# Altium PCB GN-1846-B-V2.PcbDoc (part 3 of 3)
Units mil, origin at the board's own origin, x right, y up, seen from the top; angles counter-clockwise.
Board outline 11621.85 x 2979.29 mil, 2 copper layers (Top, Bottom), stack 12.7 mil thick; 356 components, 252 nets, 1224 pads, 826 vias.
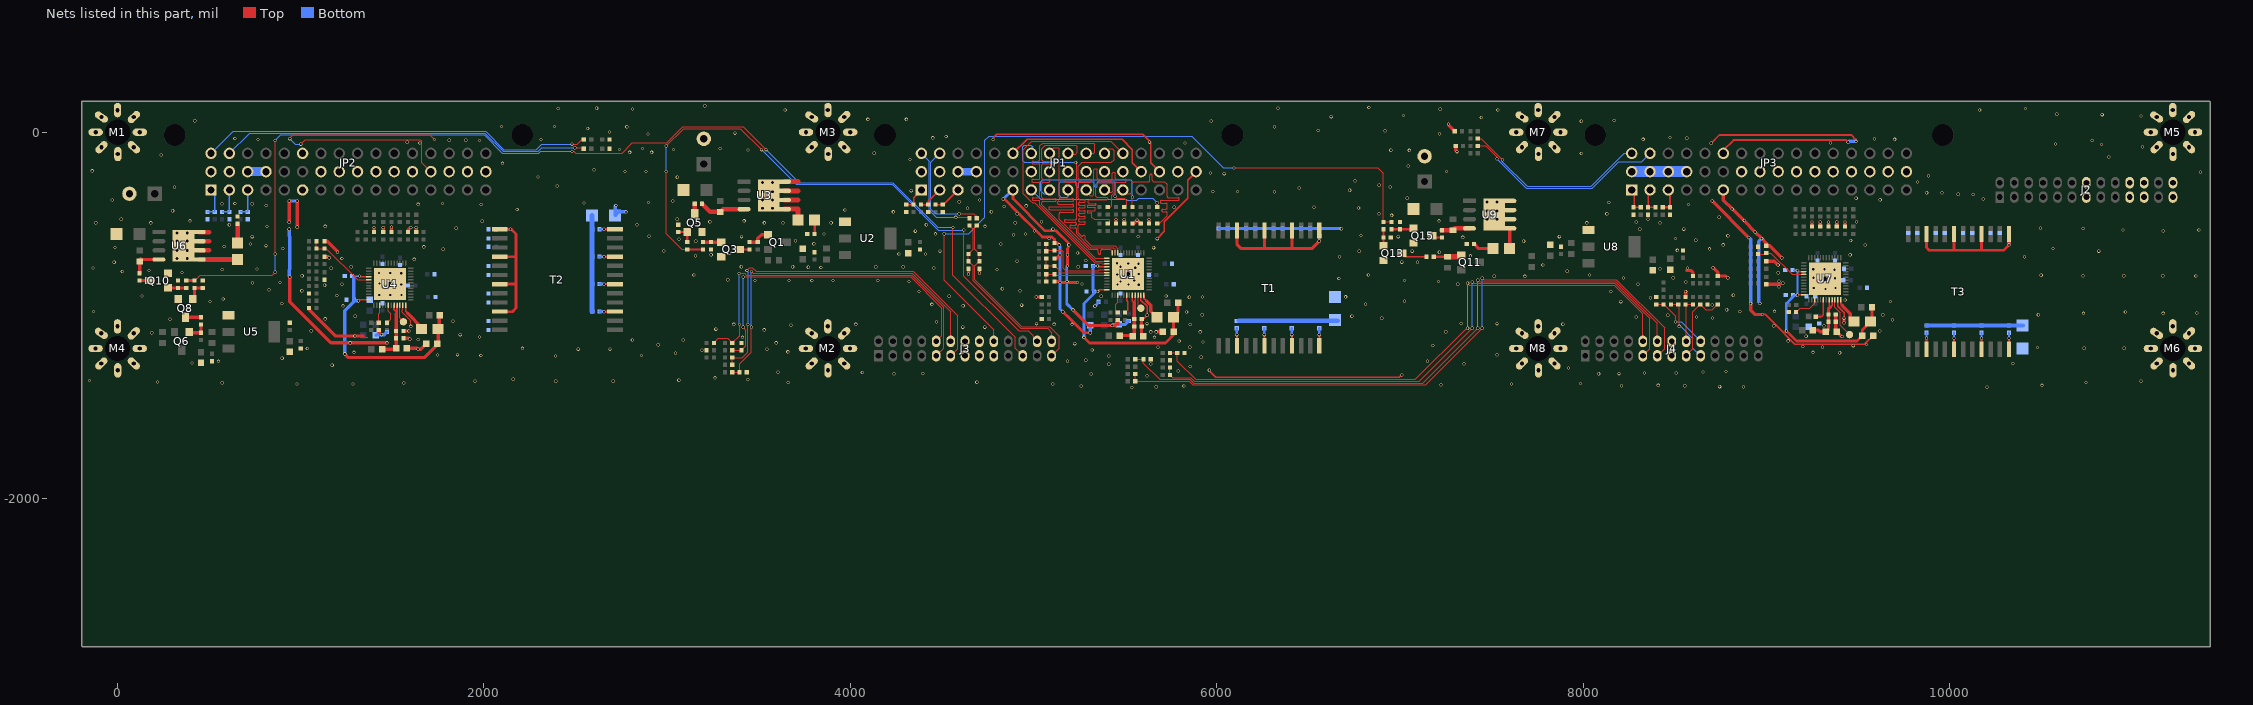
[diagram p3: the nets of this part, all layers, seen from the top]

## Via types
v1: diameter 18, hole 12, Top to Bottom, 786 vias
v2: diameter 24, hole 16, Top to Bottom, 28 vias
v3: diameter 30, hole 20, Top to Bottom, 6 vias
v4: diameter 40, hole 30, Top to Bottom, 6 vias

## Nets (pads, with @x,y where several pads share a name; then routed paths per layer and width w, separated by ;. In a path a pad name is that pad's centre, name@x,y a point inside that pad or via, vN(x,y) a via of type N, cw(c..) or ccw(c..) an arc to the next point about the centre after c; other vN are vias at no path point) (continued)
GND: C1.2 C2.2 C3.2 C4.2 C5.2 C6.2 C7.2 C8.2 C9.2 C10.2 C11.2 C12.2 C13.2 C14.2 C15.2 C16.2 C17.2 C18.1 C19.1 C20.2 C21.1 C22.1 C23.1 C24.1 C25.1 C26.1 C27.1 C28.2 C29.2 C30.2 C31.2 C32.1 C33.1 C34.2 C35.2 C36.2 C37.2 C38.2 C39.2 C40.2 C41.2 C42.2 C43.2 C44.2 C45.2 C46.2 C47.2 C48.2 C49.2 C50.2 C51.1 C52.1 C53.1 C54.1 C55.1 C56.1 C57.1 C58.1 C59.2 C60.2 C61.1 C62.2 C63.2 C64.2 C65.2 C66.1 C67.1 C68.2 C69.2 C70.2 C71.2 C72.2 C73.2 C74.2 C75.2 C76.2 C77.2 C78.2 C79.2 C80.2 C81.2 C82.2 C83.2 C84.2 C85.2 C86.1 C87.1 C88.1 C89.1 C90.1 C91.1 C92.1 C93.1 C94.2 C95.1 C96.2 C97.2 C98.2 C99.2 C100.1 C101.1 C102.2 C300.2 C301.2 C302.2 J2.13 J2.14 J2.19 J2.20 J2.21 J2.22 J2.25 J2.26 J3.13 J3.14 J3.15 J3.16 J3.17 J4.13 J4.14 JP1.A6 JP1.B7 JP1.B8 JP1.B9 JP1.B10 JP1.B11 JP1.B12 JP1.B13 JP1.B14 JP1.B15 JP1.B16 JP1.C6 JP2.A6 JP2.B7 JP2.B8 JP2.B9 JP2.B10 JP2.B11 JP2.B12 JP2.B13 JP2.B14 JP2.B15 JP2.B16 JP2.C6 JP3.A6 JP3.B7 JP3.B8 JP3.B9 JP3.B10 JP3.B11 JP3.B12 JP3.B13 JP3.B14 JP3.B15 JP3.B16 JP3.C6 M1.2 M1.3 M1.4 M1.5 M1.6 M1.7 M1.8 M1.9 M2.2 M2.3 M2.4 M2.5 M2.6 M2.7 M2.8 M2.9 M3.2 M3.3 M3.4 M3.5 M3.6 M3.7 M3.8 M3.9 M4.2 M4.3 M4.4 M4.5 M4.6 M4.7 M4.8 M4.9 M5.2 M5.3 M5.4 M5.5 M5.6 M5.7 M5.8 M5.9 M6.2 M6.3 M6.4 M6.5 M6.6 M6.7 M6.8 M6.9 M7.2 M7.3 M7.4 M7.5 M7.6 M7.7 M7.8 M7.9 M8.2 M8.3 M8.4 M8.5 M8.6 M8.7 M8.8 M8.9 Q3.2 Q5.2 Q8.2 Q10.2 Q13.2 Q15.2 R17.1 R20.1 R22.1 R28.2 R32.2 R33.2 R38.2 R41.2 R44.2 R47.2 R49.2 R51.1 R58.1 R60.1 R77.1 R78.1 R82.1 R88.2 R92.2 R93.2 R98.2 R101.2 R103.2 R107.2 R109.2 R111.1 R118.1 R120.1 R137.1 R138.1 R142.1 R148.2 R152.2 R153.2 R158.2 R161.2 R164.2 R167.2 R169.2 R171.1 R178.1 R180.1 R202.2 R203.2 R204.2 R205.2 R208.2 R209.2 R300.2 R301.2 R302.2 R303.2 R304.2 R305.2 R306.2 R307.2 R308.2 U1.47 U1.49 U2.1 U4.47 U4.49 U5.1 U7.47 U7.49 U8.1 | length 16168.3
  Top w5: v1@940,-32.5 957.5,-15 1705,-15 v1(1730,-40) ; v1(1000,-65) 1023.5,-41.5 1651.5,-41.5 1660,-50 1660,-59.11 1660,-165.51 JP2.B13@1709.84,-215.35 ; 1343.5,-1112 1350,-1118.5 1365.17,-1118.5
  Top w6: U4.47@1556.67,-944.17 1555.41,-945.43 1555.41,-969.59 1555,-970 1555,-984.04 1600,-1029.04 v1(1600,-1060)
  Top w8: v1(4780,-40) 4780,-30 4800,-10 5595,-10 5636.05,-51.05 5640,-55 5640,-167.56 JP1.B14@5687.8,-215.35 ; JP1.A6@4887.8,-115.35 4964.65,-38.5 5483.5,-38.5 5540,-95 5540,-167.56 JP1.B13@5587.8,-215.35 ; U1.47@5586.67,-889.17 5586.67,-917.12 5620.76,-951.22 v1(5620.76,-999.24) C1.2@5590,-1030 ; v1(5675,-581) 5714,-542 5714,-488.26 5841.57,-360.69 5841.57,-261.57 JP1.B16@5887.8,-215.35 ; v1(5960,-1299.11) 5960,-1303.5 5995,-1338.5 6997.29,-1338.5 v1(7010.79,-1325) ; v1(8980,-995) 8994.54,-995 9048.67,-1049.12 9156.04,-1156.5 9475,-1156.5 9538.03,-1156.5 9541.21,-1153.32 C81.2@9583.53,-1111 ; U7.47@9390.91,-915.59 9390.91,-950.91 9425,-985 v1(9425,-1015)
  Top w10: v1(8700,-60) 8745,-15 9465,-15 9490,-40 v1(9490,-50) ; JP3.A6@8765.75,-99.25 8822,-43 9350.79,-43 9435.75,-43 v1(9447.75,-55)
  Top w15: v1(4835,-365) 4841.67,-365 4916.23,-439.56 5010.39,-533.72 5048.17,-571.5 5085.79,-571.5 5101.5,-571.5 5115,-585 C27.1@5115,-605 5130,-605 v1(5140,-615) ; JP1.C6@4887.8,-315.35 4887.8,-362.8 5063.5,-538.5 5105.79,-538.5 5123.91,-538.5 5190,-604.59 5190,-614.11 5190,-629.59 5185,-634.59 5185,-669 v1(5185,-730) ; v1(5015,-900) R41.2@5045,-900 ; v1(5160,-980) 5168.5,-988.5 5168.5,-988.91 5181.09,-1001.5 5181.5,-1001.5 5219.55,-1039.55 5275,-1095 v1(5310,-1095)
  Top w18: v1(937,-491) 937,-380 939.5,-377.5 v1@942,-375 ; v1(940,-790) 940,-925.46 1164.54,-1150 v1(1270,-1150) v1(1470,-1150) ; v1@980,-520 v1(980,-519) v1(980,-375) ; R88.2@1045,-960 1045,-970 1187,-1112 v1(1295,-1112) 1340,-1112 ; C66.1@1130,-680 1150,-680 v1(1155,-685) ; C61.1@1130,-595 1145,-595 1200,-650 v1(1200,-655) ; R109.2@1400,-545 v1(1400,-520) ; R77.1@1425,-1080 1425,-1090 v1(1440,-1105) ; R107.2@1450,-545 v1(1450,-520) ; R103.2@1495,-545 v1(1495,-519.11) ; C35.2@1560,-1125 1590,-1125 v1(1595,-1130) ; C36.2@1560,-1085 v1(1590,-1085) ; C37.2@1579.53,-1180 1635,-1180 v1(1640,-1185) 1655.47,-1185 C47.2@1685.47,-1155 ; R98.2@1585,-545 1585,-535 v1(1600,-520) ; R93.2@1630,-545 v1(1630,-520) ; v1(4645,-775) R205.2@4645,-745 ; v1(4705,-770) R204.2@4705,-745 ; C33.1@5115,-815 5140,-815 v1(5145,-820) 5183.5,-820 v1(5240,-820) ; C32.1@5115,-690 5125,-690 v1(5145,-670) ; v1(5215,-970) 5300,-1055 v1(5430,-1055) 5450,-1055 5460,-1045 R20.1@5460,-1025 ; R49.2@5450,-499 5450,-477.79 v1(5450.79,-477) ; R47.2@5495,-499 5495,-477.79 v1(5495.79,-477) ; R44.2@5540,-499 5546,-499 v1(5565,-480) 5566,-480 R38.2@5585,-499 ; C3.2@5590,-1110 C1.2@5590,-1030 ; R33.2@5630,-499 5630,-477.79 v1(5630.79,-477) ; v1(5670,-1090) C13.2@5705.47,-1090 ; v1(7265,45) 7265,40 R208.2@7300,5 ; R209.2@7305,-75 7305,-99 v1(7312,-106) ; R138.1@8560,-900 v1(8560,-870) ; 8565,-755 8570.79,-755 8590,-755 8600,-765 R148.2@8600,-785 ; v1(8705,-375) v1(8905,-575) ; v1(8710,-740) 8735,-765 R161.2@8735,-785 8780,-785 v1(8790,-795) ; JP3.C6@8765.75,-315.35 8765.75,-370.75 8814.05,-419.05 8878.89,-483.89 v1(8940,-545) v1(8975,-580) 9000,-605 C95.1@9000,-620 9020,-620 v1(9085,-685) ; JP3.A6@8765.75,-115.35 JP3.A6@8765.75,-99.25 ; v1(8915,-935) 8915,-972.11 8937.89,-995 v1(8980,-995) ; C101.1@9000,-830 9070,-830 9075,-830 ; C100.1@9000,-705 9045,-705 v1(9065,-725) ; R169.2@9250,-515 v1(9250,-490) ; R167.2@9295,-515 v1(9295,-490) ; R164.2@9340,-515 v1(9340,-490) ; C69.2@9380,-995 9380,-1085.47 C71.2@9384.53,-1090 9409.53,-1115 v1(9415,-1115) ; R158.2@9385,-515 v1(9385,-490) ; v1(9425,-1040) v1(9425,-1015) ; R153.2@9430,-515 v1(9430,-490)
  Bottom w5: v1(940,-35) 970,-65 v1(1000,-65)
  Bottom w15: v1(4835,-365) 4884.65,-315.35 JP1.C6@4887.8,-315.35 ; 5145,-625 v1(5145,-670) v1(5145,-820) 5145,-965 v1(5160,-980) ; v1(5185,-730) 5181.5,-733.5 5181.5,-815 5181.5,-936.5 v1(5215,-970) ; v1(5335,-950) 5355,-930 C6.2@5355,-925 ; C21.1@6010,-525 v1@6678.79,-525
  Bottom w18: v1(937,-530) 937,-567 940,-570 940,-749.47 937,-752.47 937,-787 v1(940,-790) ; v1@942,-375 v1(980,-375) ; C50.2@1410,-1109.53 1414.53,-1105 v1(1440,-1105) 1455.47,-1105 C49.2@1470,-1090.47 ; v1(2720,-400) 2716,-404 C60.2@2716,-455 2730,-441 2730,-440 2735,-435 v1(2775,-435) ; v1(5310,-1095) C7.2@5310,-1054.53 ; v1(5430,-1055) 5435.47,-1049.53 C16.2@5465,-1049.53 5500.94,-1049.53 C15.2@5520,-1030.47 ; v1(8905,-575) 8915,-585 v1(8915,-935) ; v1(8965,-935) 8965,-932.47 8958.76,-926.24 8958.76,-596.24 v1(8975,-580) ; v1(9447.75,-55) 9452.75,-50 v1(9490,-50)
  other v1: 5536,-1394.11 10205.79,-1392 8875.79,-1390 5670,-1389.11 8745.79,-1389 5260.79,-1386 5820.79,-1385 8210,-1384.11 8555,-1384.11 8410.79,-1382 10505.79,-1382 7225,-1379.11 979,-1374.11 1285,-1374.11 5105,-1374.11 7610,-1374.11 7985.79,-1372 1562,-1369.11 570.79,-1368 3660.79,-1366 10745.79,-1366 4690.79,-1365 218,-1364.11 2705.79,-1360 11045.79,-1360 1951,-1359.11 2392,-1359.11 -154.21,-1356 3064,-1354.11 3440,-1350 2160,-1349.11 3260.79,-1341 5620,-1329.11 5315,-1320 4238,-1319.11 8085,-1319.11 8195.79,-1318 4395.79,-1317 8335,-1314.11 8509,-1314.11 4065.79,-1312 3605,-1310 8655,-1309.11 8780.79,-1306 5790,-1304.11 7921,-1287 5856,-1279.11 1170.79,-1272 5410.79,-1267 5640,-1265 7350,-1264.11 10345.79,-1263 405.79,-1260 550.79,-1251 5185.79,-1250 7150.79,-1250 5285,-1245 898,-1234.11 5915.79,-1228 2390.79,-1222 5411,-1222.11 1983,-1219.11 2860,-1219.11 1745.79,-1216 7530.79,-1215 1855,-1214.11 3045.79,-1207 9400.79,-1204 1290.79,-1202 9255.79,-1202 3659,-1199.11 3190,-1190 5320,-1189.11 3545,-1185 2515,-1184.11 2688,-1184.11 1035.79,-1181 2210,-1180 10736,-1179.11 10955,-1179.11 10480.79,-1175 5680,-1174.11 5853,-1174.11 9307,-1174.11 9200,-1170 9475,-1165 7179,-1164.11 2950.79,-1160 9547,-1159.11 5225,-1154.11 3595,-1150 5925.79,-1145 5795,-1140 9120,-1139.11 2810,-1134.11 3088,-1134.11 1640.79,-1132 3410.79,-1120 5660,-1120 1975.79,-1118 9218,-1114.11 1870.79,-1105 185.79,-1095 5640,-1090 5910,-1090 7250,-1089.11 9620,-1085 1057,-1084.11 3530,-1079.11 3265.79,-1075 4614,-1064.11 4734,-1064.11 9040.79,-1057 9315,-1057.11 3675.79,-1054 5855.79,-1050 3363,-1049.11 4030,-1049.11 5113,-1049.11 5210,-1049.11 7890,-1048 5015.79,-1045 5620,-1045 7530.79,-1045 7335,-1044.11 4470,-1035 1830.79,-1032 9690,-1024.11 285.79,-1021 1133,-1019.11 6901,-1016 8707,-1014.11 8290,-1009.11 8619,-1009.11 1297,-1005 6738,-1005 8462,-999.11 9635.79,-997 5920.79,-996 10485.79,-996 10732,-989.11 11168,-989.11 11350.79,-987 5835.79,-982 10960.79,-982 -132,-979.11 8856,-979.11 9045.79,-978 8784,-969.11 1230.79,-948 4615.79,-947 4935,-944.11 8705.79,-943 4445,-940 6812,-939 895.79,-935 8205.79,-925 504,-924.11 9678,-924.11 7025.79,-923 9430.79,-916 575.79,-910 8368,-904.11 5850.79,-901 5923,-899.11 6704,-899 4540,-895 5370,-895 133,-894.11 5724,-894.11 1195.79,-891 8820.79,-890 1428,-889 1488,-889 1549,-889 4375,-870 8150.79,-870 1005.79,-865 4925.79,-865 825.79,-860 9324,-856 4830,-854.11 9379,-851 9259,-850 9070,-844.11 1130,-835 5575,-833 1548,-832 5458,-832 5519,-832 1225,-830 7315.79,-830 8300,-830 5265,-829.11 1429,-826 9090.79,-825 735.79,-822 885.79,-820 8560.79,-818 4320,-815 5183.5,-815 5475,-815 7210.79,-815 9070,-814.11 5550,-810 7025.79,-810 3480,-809.11 3665,-809.11 3790,-809.11 3905,-809.11 4150,-809.11 3330.79,-805 6667,-799.11 9376,-797 8220.79,-796 9258,-795 8493,-794.11 7682,-787.11 7515,-786.11 11345.79,-785 1007,-784.11 10729,-784.11 10952,-784.11 11165,-784.11 10500.79,-781 3145.79,-779 6828,-779.11 8035,-779.11 5457,-776 5575,-774 1548,-770 1488,-769 1427,-768 9065.79,-767 350.79,-766 25.79,-760 7914,-759.11 170.79,-755 9372,-751 570.79,-750 4800.79,-750 9257,-748 9318,-748 760.79,-747 8420,-745 1165.79,-743 -134.21,-741 4455.79,-741 8570.79,-741 5555,-740 3839,-739.11 3770.79,-737 3685,-735 5475,-735 1275,-734.11 3405,-734.11 4139,-734.11 4289,-734.11 5244,-734.11 7780.79,-725 5573,-718 5517,-717 5456,-715 -19.21,-710 7095.79,-710 7010,-709.11 4910,-704.11 5285,-700 1619,-694.11 1224,-689.11 6671,-680 10410,-680 7385.79,-675 3155,-674.11 3240,-669.11 5185.79,-669 9458,-669.11 4265,-665 4410,-665 3340,-660 5240.79,-659 7215.79,-655 6778,-650 4489,-649.11 7068,-649.11 10815,-649.11 2980.79,-648 8515,-645 1777,-639.11 8690.79,-637 900.79,-635 10565.79,-635 5655.79,-630 -15,-629.11 1670.79,-626 582,-624.11 810,-619.11 9540.79,-616 8765.79,-615 5193,-614.11 725,-610 4820.79,-610 3800.79,-609 3155.79,-595 7675.79,-595 3700.79,-593 9460.79,-591 8615,-590 3065,-584.11 5085.79,-580 8505,-580 7343,-574.11 735,-570 3405.79,-570 6990.79,-570 7870.79,-570 5572,-569.11 2900.79,-568 8790.79,-565 6788,-564.11 4890.79,-560 3855.79,-556 4955.79,-556 4465,-555 4355,-540 5005,-539.11 11168,-539.11 10948,-534.11 11362,-534.11 5105.79,-530 8310,-530 8550,-529.11 6680.79,-527 10730.79,-526 1849,-524.11 10497,-524.11 815,-515 1133,-514.11 4735,-514.11 610,-505 2835.79,-505 3155.79,-505 4415,-505 180.79,-495 3530.79,-495 8020,-495 -120,-494.11 3632,-494.11 3895,-494.11 4900,-494.11 8420,-494.11 8290.79,-490 3233,-489.11 5044,-489.11 9493,-489.11 1990.79,-486 395,-484.11 3420,-484.11 7214,-484.11 8880.79,-482 20,-475 3055,-475 8355,-475 8744,-464.11 6955,-454.11 4910.79,-445 6885.79,-445 8130,-445 4235,-435 4770,-434.11 300,-429.11 3970,-425 2180.79,-422 8814,-419.11 4640,-415 6775,-414.11 6530.79,-410 5768,-409.11 4840,-405 4960.79,-402 810.79,-400 8575.79,-395 1640.79,-394 1985,-394.11 570,-390 735,-390 640,-389.11 1773,-389.11 2545.79,-386 2898,-384.11 8140,-384.11 4595,-380 937,-375 3030,-375 -29.21,-370 4705,-370 9622,-369.11 10185,-365 9490.79,-361 7040.79,-360 10130.79,-340 10048,-339.11 9875.79,-330 9960,-330 6315.79,-325 5979,-324.11 6114,-324.11 4333,-319 6725.79,-317 6450.79,-305 310.79,-300 6948,-299.11 2400,-294.11 6887,-289.11 9825.79,-272 6755,-265 3055.79,-246 2295,-245 9885.79,-238 6040.79,-226 5965.79,-223 11370.79,-219 2770,-214.11 2884,-214.11 7255,-214.11 -139.21,-211 2600.79,-205 7046,-184.11 2100.79,-170 4326,-149 10870,-135 238,-124.11 7990.79,-116 4130.79,-115 2795,-110 2915,-110 7052,-99.11 6950.79,-98 3440.79,-97 2740,-94.11 3034,-94.11 2865,-89.11 3290,-89.11 11054,-79.11 10830.79,-67 10579,-64.11 1650,-59.11 5827,-59.11 9350.79,-57 1580.79,-55 5633,-54.11 1975.79,-45 10780,-45 1810,-44.11 1900,-44.11 765.79,-40 2310.79,-40 8328,-39.11 9701,-39.11 9590.79,-36 640,-34.11 8565.79,-33 4450,-31 8475,-29.11 4523,-23 2895,-10 7216,-8 3370.79,-5 2685,0.89 6919,8 6554,9 2565.79,20 2780,30 6315.79,30 2095,30.89 2385,30.89 7990.79,60 5970,60.89 420.79,63 8170.79,64 4095.79,70 4305.79,70 7445,80 6625,85 11045.79,88 7020,90.89 10834,95.89 10585.79,98 3644,120.89 7535,120.89 10165,120.89 7220.79,125 2810.79,127 2405.79,129 10415,130 2615,130.89 6335,130.89 6830.79,135 3205,145
MAC_MDC: C32.2 R30.1 R37.2 U1.30 | length 393
  Top w5: R30.1@5070,-690 R37.2@5070,-735 5075,-730 C32.2@5115,-730 5151.34,-766.34 U1.30@5400.84,-766.34
MAC_MDIO: C33.2 R31.1 R39.2 U1.31 | length 377.9
  Top w5: R31.1@5070,-815 R39.2@5070,-775 C33.2@5105,-775 ; C33.2@5107.92,-772.08 C33.2@5105,-775 ; U1.31@5400.84,-782.08 5122.08,-782.08 C33.2@5115,-775 C33.2@5105,-775
NetB1_1: B1.1 C1.1 C2.1 C3.1 U1.44 U1.45 | length 344.6
  Top w8: U1.44@5539.42,-889.17 5539.42,-919.42 5550.47,-930.47 5550.47,-924.53 5555.17,-919.83 U1.45@5555.17,-889.17
  Top w18: B1.1@5479.53,-1115 5479.53,-1110 5540.47,-1110 5550.47,-1110 5550.47,-930.47
NetB2_2: B2.2 C11.1 C12.1 C13.1 L1.1 U1.28 U1.36 | length 1282.6
  Top w8: v1(5350,-870) 5359.18,-860.82 U1.36@5400.84,-860.82 ; v1(5350,-730) 5355,-735 5355.16,-734.84 U1.28@5400.84,-734.84
  Top w16: v1(5275,-1120) 5305,-1150 5720,-1150 5772.26,-1097.74 C13.1@5764.53,-1090 5764.53,-1010.47 L1.1@5765,-1010 5789.53,-985.47 B2.2@5789.53,-930
  Bottom w12: C12.1@5325,-730 v1(5350,-730) ; C11.1@5330,-870 v1(5350,-870)
  Bottom w16: v1(5275,-1120) 5275,-1090 ; 5275,-1100 5275,-1090 ; C11.1@5325,-864.53 C12.1@5325,-730 ; C11.1@5330,-870 5330,-880 5275,-935 5275,-1090
NetB4_1: B4.1 C35.1 C36.1 C37.1 U4.44 U4.45 | length 356.4
  Top w10: U4.44@1509.42,-944.17 1509.42,-969.42 1525,-985 ; 1525.17,-984.83 U4.45@1525.17,-944.17
  Top w18: B4.1@1444.53,-1185 1515.47,-1185 C37.1@1520.47,-1180 1520.47,-989.53
NetB5_2: B5.2 C45.1 C46.1 C47.1 L2.1 U4.28 U4.36 | length 1349
  Top w8: v1(1315,-920) 1320,-920 1324.18,-915.82 U4.36@1370.84,-915.82 ; v1(1320,-785) 1325,-790 1330,-790 1330.16,-789.84 U4.28@1370.84,-789.84
  Top w18: v1(1240,-1210) 1260,-1230 1675,-1230 1747.26,-1157.74 1750,-1155 L2.1@1750,-1075
  Top w20: B5.2@1754.53,-1005 1759.53,-1005 1765,-1005 1764.76,-1005.24 1755,-1015 1755,-1075 L2.1@1755,-1080
  Top w24: L2.1@1745,-1075 1745,-1070 L2.1@1750,-1075 L2.1@1755,-1080
  Bottom w8: C45.1@1289.53,-790 1294.53,-785 v1(1320,-785)
  Bottom w18: v1(1240,-1210) 1240,-974.53 1290,-924.53 C46.1@1290,-915 1295,-920 v1(1315,-920) ; C46.1@1289.53,-915 C45.1@1289.53,-790
NetB7_1: B7.1 C69.1 C70.1 C71.1 U7.44 U7.45 | length 312.7
  Top w8: U7.44@9343.66,-915.59 9343.66,-948.66 9350,-955 9359.41,-945.59 U7.45@9359.41,-915.59
  Top w18: B7.1@9254.53,-1080 9285,-1080 9295,-1090 9320.47,-1090 9322.97,-1092.5 9325.47,-1095 9327.97,-1092.5 9340,-1080.47 9340,-965 9350,-955
NetB8_2: B8.2 C79.1 C80.1 C81.1 L3.1 U7.28 U7.36 | length 1080.7
  Top w8: v1(9170,-890) 9173.39,-886.61 U7.36@9205.04,-886.61 ; v1(9170,-755) 9175,-755 9180.63,-760.63 U7.28@9205.04,-760.63
  Top w15: v1(9110,-1085) 9165,-1140 9495.47,-1140 C81.1@9524.47,-1111 9524.47,-1079.53 L3.1@9570,-1034 9577.53,-1026.47 B8.2@9577.53,-956
  Bottom w12: C79.1@9153,-755 v1(9170,-755) v1(9170,-890)
  Bottom w15: v1(9110,-1085) 9110,-935 9155,-890 v1(9170,-890)
NetC17_1: C17.1 T1.1 T1.4 T1.7 T1.10 | length 927.6
  Top w12: v1(6560,-595) 6560.79,-594.21 T1.1@6560.79,-535.84
  Top w18: T1.10@6110.79,-535.84 6110.79,-610.79 6135,-635 6260,-635 ; T1.7@6260.79,-535.84 6260.79,-634.21 6260,-635 ; 6410.79,-624.21 T1.4@6410.79,-535.84 6410.79,-634.21 6410,-635 ; v1(6560,-595) 6520,-635 6410,-635 ; 6260,-635 6410,-635
  Bottom w12: v1(6560,-595) C17.1@6560,-565
NetC20_1: C20.1 R1.2 R2.2 R3.2 R11.2 | length 540
  Bottom w24: R1.2@6120,-1030 6645,-1030 C20.1@6660,-1030
NetC27_2: C27.2 R10.2 R12.2 U1.29 | length 487.1
  Top w5: R12.2@5070,-600 5070,-645 C27.2@5115,-645 ; C27.2@5125,-645 C27.2@5115,-645 ; U1.29@5400.84,-750.59 5360,-750.59 5354.25,-756.34 5176.34,-756.34 5161.5,-741.5 5161.5,-651.5 5155,-645 C27.2@5115,-645
NetC59_1: C59.1 T2.1 T2.4 T2.7 T2.10 | length 861.6
  Top w15: T2.10@2085.84,-979.21 2086.63,-980 2155,-980 2175,-960 2175,-830 ; T2.7@2085.84,-829.21 2174.21,-829.21 2175,-830 ; T2.4@2085.84,-679.21 2174.21,-679.21 2175,-680 ; T2.1@2085.84,-529.21 2144.21,-529.21 v1(2145,-530) 2150,-530 2175,-555 2175,-680 ; 2175,-830 2175,-680
  Bottom w15: C59.1@2065,-530 v1(2145,-530)
NetC60_1: C60.1 R61.2 R62.2 R63.2 R69.2 | length 524.5
  Bottom w28: C60.1@2590,-455 2590,-978.41 R61.2@2590.8,-979.21
NetC61_2: C61.2 R71.2 R72.2 U4.29 | length 396.5
  Top w5: R72.2@1085,-595 R71.2@1085,-635 C61.2@1130,-635 1140,-635 1310.59,-805.59 U4.29@1370.84,-805.59
NetC85_1: C85.1 T3.1 T3.4 T3.7 T3.10 | length 810.6
  Top w15: T3.10@9875,-555.04 9875,-630 9890,-645 10025,-645 ; T3.7@10025,-555.04 10025,-645 ; T3.4@10175,-555.04 10175,-640 10170,-645 ; T3.1@10325,-555.04 v1(10325,-615) 10295,-645 10170,-645 ; 10025,-645 10170,-645
  Bottom w15: v1(10325,-615) C85.1@10325,-590
NetC94_1: C94.1 R121.2 R122.2 R123.2 R129.2 | length 525
  Bottom w24: R121.2@9875,-1055 C94.1@10400,-1055
NetC95_2: C95.2 R131.2 R132.2 U7.29 | length 340.3
  Top w5: R132.2@8955,-625 R131.2@8955,-665 8995,-665 C95.2@9000,-660 9025,-660 9141.38,-776.38 U7.29@9205.04,-776.38
NetJ3_9: J3.9 R74.2 R75.2 | length 1989.8
  Top w5: R74.2@3255,-1150 3280,-1125 3330,-1125 R75.2@3355,-1150 3395,-1110 v1(3395,-1050) ; v1(3393.61,-771.39) 3394.5,-770.5 3422.92,-770.5 3432.42,-780 4334.14,-780 4510,-955.86 4510,-1178.98 J3.9@4468.5,-1220.47
  Bottom w5: v1@3393.61,-1048.61 v1(3393.61,-771.39)
NetJ3_10: J3.10 R76.2 R78.2 | length 1811.8
  Top w5: R76.2@3355,-1190 R78.2@3400,-1190 ; R78.2@3405,-1190 3430,-1165 3430,-1080 v1(3415,-1065) ; v1(3415,-790) 4330,-790 4500,-960 4500,-1110.24 J3.10@4468.5,-1141.73
  Bottom w5: v1(3415,-1065) v1(3415,-790)
NetJ3_11: J3.11 R79.2 R80.2 | length 2081
  Top w5: R80.2@3355,-1270 R79.2@3355,-1230 3410,-1230 3440,-1200 v1(3440,-1050) ; v1(3435,-755) 3450,-740 3465,-740 3485,-760 4342.43,-760 4585,-1002.57 4585,-1182.72 J3.11@4547.24,-1220.47
  Bottom w5: v1(3435,-755) 3443.5,-763.5 v1@3443.5,-1046.5
NetJ3_12: J3.12 R81.2 R82.2 | length 1957.6
  Top w5: R81.2@3355,-1310 R82.2@3395,-1310 3395,-1265 3460,-1200 v1(3460,-1065) ; v1(3460,-760) 3470,-770 4338.28,-770 4547.24,-978.96 J3.12@4547.24,-1141.73
  Bottom w5: v1(3460,-1065) v1(3460,-760)
NetJ3_18: J3.18 R170.2 R179.2 | length 3957.2
  Top w5: v1(4513,-554) 4513,-808 4783.47,-1078.47 J3.18@4783.47,-1141.73 ; v1(6095,-195) 6880,-195 6910,-225 R170.2@6910,-490 R179.2@6955,-490
  Bottom w5: v1(4513,-554) 4646,-554 4735,-465 4735,-45 4758,-22 5862.86,-22 6035.86,-195 v1(6095,-195)
NetJ3_21: J3.21 R110.2 R119.2 | length 6131.9
  Top w5: R110.2@420,-810 450,-780 845,-780 v1(860,-765) ; v1(860,-665) v1(860,-45) ; v1(2480,-105) 2490,-105 2500,-115 2753.5,-115 2810,-58.5 2997.36,-58.5 3085.86,30 3415,30 v1(3540,-95) ; v1(4560,-520) 4560,-780 4900,-1120 4900,-1179.53 J3.21@4940.95,-1220.47
  Top w18: R119.2@375,-810 R110.2@420,-810
  Bottom w5: v1(860,-765) v1(860,-665) ; v1(860,-45) 890,-15 2000.86,-15 2100.86,-115 2300,-115 2310,-105 v1(2480,-105) ; v1(3540,-95) 3720,-275 4231.72,-275 4476.72,-520 v1(4560,-520)
NetJ3_24: J3.24 R50.2 R59.2 | length 3412.7
  Top w5: v1(2995,-215) 2995,-555 3080,-640 R59.2@3110,-640 R59.2@3120,-640 ; v1(2995,-75) 3090,20 3400,20 v1(3515,-95) ; v1@4620,-534 4620,-785 4920,-1085 4970,-1085 5019.69,-1134.69 J3.24@5019.69,-1141.73
  Top w12: R59.2@3120,-640 R50.2@3195,-640
  Bottom w5: v1(2995,-215) v1(2995,-75) ; v1(3515,-95) 3705,-285 4227.57,-285 4479.07,-536.5 4616.5,-536.5 v1(4619,-534)
NetJ4_9: J4.9 R13.2 R14.2 | length 3351.1
  Top w5: R14.2@5745,-1285 R13.2@5745,-1325 5760,-1340 5858.28,-1340 5878.28,-1360 7105,-1360 v1(7395,-1070) ; v1(7395,-818) 7402,-825 8174.14,-825 8365,-1015.86 8365,-1182.24 J4.9@8326.77,-1220.47 ; v1@7395,-815 v1@7396.5,-816.5
  Bottom w5: v1(7395,-1070) v1(7395,-818)
NetJ4_10: J4.10 R15.2 R17.2 | length 3252.9
  Top w5: R15.2@5745,-1205 R17.2@5785,-1205 5785,-1250 5885,-1350 7085,-1350 7362.67,-1072.33 7370,-1072.33 7372.33,-1072.33 v1(7370,-1070) ; v1(7370,-825) 7380,-835 8170,-835 8326.77,-991.77 J4.10@8326.77,-1141.73
  Bottom w5: v1(7370,-1070) v1(7370,-825)
NetJ4_11: J4.11 R18.2 R19.2 | length 3621
  Top w5: R18.2@5555,-1320 R19.2@5555,-1360 5850,-1360 5870,-1380 7140,-1380 v1(7450,-1070) ; v1(7450,-797) 7458,-805 8182.43,-805 8445,-1067.57 8445,-1180.98 J4.11@8405.51,-1220.47
  Bottom w5: v1(7450,-1070) v1(7450,-797)
NetJ4_12: J4.12 R21.2 R22.2 | length 3502.4
  Top w5: R21.2@5555,-1240 R22.2@5600,-1240 5600,-1260 5690,-1350 5854.14,-1350 5874.14,-1370 7125.86,-1370 v1@7425.43,-1070.43 ; v1(7425,-808) 7425,-810 7430,-815 8178.28,-815 8405.51,-1042.23 J4.12@8405.51,-1141.73 ; v1@7425,-805 v1@7426.5,-806.5
  Bottom w5: v1(7425,-1070) v1(7425,-808)
NetJ4_15: J4.15 R134.2 R135.2 | length 432.2
  Top w5: J4.15@8562.99,-1220.47 8600,-1183.47 8600,-980 R135.2@8640,-940 8670,-970 8705,-970 R134.2@8735,-940
NetJ4_16: J4.16 R136.2 R138.2 | length 243
  Top w5: J4.16@8562.99,-1141.73 8562.99,-942.99 R138.2@8560,-940 R136.2@8600,-940
NetJ4_17: J4.17 R139.2 R140.2 | length 375.7
  Top w5: R140.2@8480,-940 R139.2@8520,-940 8525,-945 v1(8525,-1060)
  Bottom w5: v1(8525,-1060) 8533.15,-1060 8600,-1126.85 8600,-1178.74 J4.17@8641.73,-1220.47
NetJ4_18: J4.18 R141.2 R142.2 | length 342.9
  Top w5: R142.2@8400,-940 R141.2@8440,-940 8505,-1005 v1(8505,-1035)
  Bottom w5: v1(8505,-1035) 8535,-1035 J4.18@8641.73,-1141.73
NetJP1_A1: JP1.A1 R52.1 | length 565.8
  Top w5: v1(4575,-465) 4645,-465 R52.1@4650,-470
  Bottom w5: JP1.A1@4387.8,-115.35 4430,-157.56 4430,-425 4470,-465 v1(4575,-465)
NetJP1_A2: JP1.A2 R53.1 | length 601
  Top w5: v1(4595,-445) 4675,-445 4690,-460 R53.1@4690,-470
  Bottom w5: JP1.A2@4487.8,-115.35 4440,-163.15 4440,-420 4465,-445 v1(4595,-445)
NetJP1_B1: JP1.B1 JP1.B2 JP1.B3 JP1.B4 LED3.A U3.5 U3.6 U3.7 U3.8 U3.9 | length 472.9
  Top w28: U3.5@3640.47,-420 3715,-420 3715,-479.61 3715,-494.29 LED3.A@3715.32,-494.61 ; U3.6@3640.47,-370 3715,-370 ; U3.7@3640.47,-320 3715,-320 ; U3.8@3640.47,-270 3715,-270
  Bottom w40: JP1.B3@4587.8,-215.35 JP1.B4@4687.8,-215.35
  other v2: 3520,-415 3575,-415 3520,-370 3575,-370 3520,-325 3575,-325 3520,-275 3575,-275
NetJP1_C1: JP1.C1 R306.1 R311.1 | length 137.4
  Top w8: R306.1@4305,-395 R311.1@4345,-395 4345,-358.15 JP1.C1@4387.8,-315.35
NetJP1_C2: JP1.C2 R307.1 R310.1 | length 145.7
  Top w8: R310.1@4385,-395 R307.1@4425,-395 4425,-378.15 JP1.C2@4487.8,-315.35
NetJP1_C3: JP1.C3 R308.1 R309.1 | length 173.9
  Top w8: R309.1@4465,-395 4508.15,-395 JP1.C3@4587.8,-315.35 JP1.C3@4569.65,-315.35
NetJP2_A1: JP2.A1 R112.1 | length 2149.2
  Top w5: v1(2480,-65) 2510,-65 2535,-40 R112.1@2545,-40
  Bottom w5: JP2.A1@509.84,-115.35 630.2,5 2009.14,5 2109.14,-95 2285,-95 2315,-65 v1(2480,-65)
NetJP2_A2: JP2.A2 R114.1 | length 2032.6
  Top w5: v1(2495,-85) 2535,-85 2540,-90 R114.1@2545,-90
  Bottom w5: JP2.A2@609.84,-115.35 720.2,-5 2005,-5 2105,-105 2295,-105 2315,-85 v1(2495,-85)
NetJP2_B1: JP2.B1 JP2.B2 JP2.B3 JP2.B4 LED2.A U6.5 U6.6 U6.7 U6.8 U6.9 | length 473.3
  Top w25: U6.5@445.47,-695 584.29,-695 ; U6.6@445.47,-645 500,-645 ; U6.7@445.47,-595 500,-595 ; U6.8@445.47,-545 500,-545 ; 584.61,-694.68 584.29,-695 ; LED2.A@654.61,-694.68 654.29,-695 584.29,-695
  Bottom w50: JP2.B3@709.84,-215.35 JP2.B4@809.84,-215.35
  other v2: 325,-690 380,-690 325,-645 380,-645 325,-595 380,-595 325,-550 380,-550
NetJP2_C1: JP2.C1 R303.1 R314.1 | length 168
  Bottom w8: R303.1@490,-435 R314.1@530,-435 530,-335.51 JP2.C1@509.84,-315.35
NetJP2_C2: JP2.C2 R304.1 R313.1 | length 159.5
  Bottom w8: R313.1@570,-435 R304.1@610,-435 JP2.C2@610,-315.51
NetJP2_C3: JP2.C3 R305.1 R312.1 | length 159.7
  Bottom w8: R312.1@670,-435 R305.1@710,-435 710,-315.51 JP2.C3@709.84,-315.35
NetJP3_A1: JP3.A1 R172.1 | length 1059.2
  Top w5: R172.1@7425,-35 7445,-35 7524.76,-114.76 ; 7510,-100 7524.76,-114.76 ; v1(7560,-150) 7524.76,-114.76 ; JP3.A1@8265.75,-115.35 JP3.A1@8275.35,-115.35
  Bottom w5: v1(7560,-150) 7560,-160 7695,-295 8045,-295 8224.65,-115.35 JP3.A1@8265.75,-115.35
NetJP3_A2: JP3.A2 R173.1 | length 1114.5
  Top w5: R173.1@7425,-75 7470,-75 7530,-135 v1(7530,-145) ; JP3.A2@8364.65,-115.35 JP3.A2@8365.75,-115.35
  Bottom w5: v1@7535,-150 7690,-305 8050,-305 8195,-160 8321.1,-160 JP3.A2@8365.75,-115.35
NetJP3_B1: JP3.B1 JP3.B2 JP3.B3 JP3.B4 LED1.A U9.5 U9.6 U9.7 U9.8 U9.9 | length 410.7
  Top w18: LED1.A@7599.68,-635.39 7600.47,-634.59 U9.5@7600.47,-525
  Bottom w60: JP3.B1@8265.75,-215.35 JP3.B2@8365.75,-215.35 JP3.B3@8465.75,-215.35 JP3.B4@8565.75,-215.35
  other v2: 7475,-475 7530,-475 7475,-430 7530,-430 7475,-380 7530,-380
NetJP3_C1: JP3.C1 R300.1 R315.1 | length 140.5
  Top w8: JP3.C1@8265.75,-315.35 8280,-329.61 R300.1@8280,-410 ; R300.1@8275,-410 R300.1@8280,-410 ; R315.1@8315,-410 R300.1@8280,-410
NetJP3_C2: JP3.C2 R301.1 R316.1 | length 139.1
  Top w8: JP3.C2@8365.75,-315.35 8355,-326.1 R301.1@8355,-410 R316.1@8395,-410
NetJP3_C3: JP3.C3 R302.1 R317.1 | length 138.5
  Top w12: R317.1@8435,-410 R302.1@8475,-410 8475,-324.61 JP3.C3@8465.75,-315.35
NetL1_2: L1.2 U1.48 | length 167.1
  Top w10: U1.48@5602.41,-889.17 5602.41,-907.41 5617.41,-922.41
  Top w18: 5617.41,-922.41 5640,-945 5640,-977 L1.2@5673,-1010 L1.2@5690,-1010
NetL2_2: L2.2 U4.48 | length 171.3
  Top w10: U4.48@1572.41,-944.17 1572.41,-977.41 1582.65,-987.65
  Top w18: 1582.65,-987.65 1664,-1069 L2.2@1670,-1075
NetL3_2: L3.2 U7.48 | length 137.8
  Top w8: U7.48@9406.65,-915.59 9406.65,-936.65 9415,-945
  Top w18: 9415,-945 9415,-947.53 9458.74,-991.26 9458.74,-1025.74 L3.2@9463,-1030
NetLED1_K: LED1.K R178.2 | length 115.2
  Top w18: R178.2@7405,-610 7430,-635 7509.29,-635 LED1.K@7509.68,-635.39
NetLED2_K: LED2.K R118.2 | length 104.8
  Top w25: LED2.K@654.61,-604.68 655,-604.29 R118.2@655,-500
NetLED3_K: LED3.K R58.2 | length 75.5
  Top w12: R58.2@3805,-555 3805.32,-554.68 LED3.K@3805.32,-479.61
NetQ1_1: Q1.1 R35.2 R42.1 | length 128.3
  Top w18: R42.1@3450,-600 R35.2@3495,-600 3495,-580 3515,-560 Q1.1@3550,-560
NetQ3_1: Q3.1 R50.1 R51.2 | length 100
  Top w18: R50.1@3195,-600 Q3.1@3295,-600
NetQ3_3: Q3.3 R42.2 | length 55
  Top w12: Q3.3@3395,-640 R42.2@3450,-640
NetQ5_1: Q5.1 R59.1 R60.2 | length 105
  Top w12: R60.2@3060,-545 Q5.1@3110,-545 R59.1@3110,-600
NetQ5_3: Q5.3 R57.1 | length 55
  Top w24: Q5.3@3150,-445 R57.1@3150,-390
NetQ6_1: Q6.1 R95.2 R104.1 | length 112.1
  Top w18: Q6.1@390,-1090 395,-1095 R95.2@455,-1095 R104.1@455,-1050
NetQ8_1: Q8.1 R110.1 R111.2 | length 109.1
  Top w18: Q8.1@410,-910 420,-900 R110.1@420,-850 R111.2@465,-850
NetQ8_3: Q8.3 R104.2 | length 85
  Top w18: Q8.3@370,-1010 R104.2@455,-1010
NetQ10_1: Q10.1 R119.1 R120.2 | length 100
  Top w18: Q10.1@275,-850 R119.1@375,-850
NetQ10_3: Q10.3 R117.1 | length 55
  Top w18: R117.1@120,-810 Q10.3@175,-810
NetQ11_1: Q11.1 R155.2 R163.1 | length 154.1
  Top w12: R163.1@7185,-680 R155.2@7260,-680
  Top w30: R155.2@7260,-680 7325,-680 Q11.1@7335,-670
NetQ13_1: Q13.1 R170.1 R171.2 | length 90
  Top w10: Q13.1@6910,-620 R170.1@6910,-530
NetQ13_3: Q13.3 R163.2 | length 143.3
  Top w10: Q13.3@7010,-660 7030,-680 R163.2@7145,-680
NetQ15_1: Q15.1 R179.1 R180.2 | length 122.1
  Top w12: R179.1@6955,-530 7070,-530 Q15.1@7075,-525
NetQ15_3: Q15.3 R177.1 | length 59.1
  Top w12: Q15.3@7175,-565 7185,-575 R177.1@7230,-575
NetR1_1: R1.1 T1.15 | length 96.1
  Top w12: v1(6110,-1105) 6110.79,-1105.79 T1.15@6110.79,-1165.76
  Bottom w12: v1(6110,-1105) R1.1@6110,-1070
NetR2_1: R2.1 T1.18 | length 96.1
  Top w12: v1(6260,-1105) 6260.79,-1105.79 T1.18@6260.79,-1165.76
  Bottom w12: v1(6260,-1105) R2.1@6260,-1070
NetR3_1: R3.1 T1.21 | length 96.1
  Top w12: v1(6410,-1105) 6410.79,-1105.79 T1.21@6410.79,-1165.76
  Bottom w12: v1(6410,-1105) R3.1@6410,-1070
NetR11_1: R11.1 T1.24 | length 96.1
  Top w12: v1(6560,-1105) 6560.79,-1105.79 T1.24@6560.79,-1165.76
  Bottom w12: v1(6560,-1105) R11.1@6560,-1070
NetR16_2: R16.2 U1.42 | length 88.8
  Top w8: U1.42@5507.93,-889.17 5507.93,-917.93 5515,-925 5515,-975
NetR20_2: R20.2 U1.39 | length 104.5
  Top w5: R20.2@5460,-985 5449.93,-974.93 5449.93,-940.07 5460.68,-929.32 U1.39@5460.68,-889.17
NetR54_1: R54.1 R57.2 U3.4 | length 254.9
  Top w24: R57.2@3190,-390 3235,-435 R54.1@3290,-435 3305,-420 U3.4@3420,-420
NetR61_1: R61.1 T2.15 | length 85.6
  Top w8: T2.15@2714.97,-980 T2.15@2715.76,-979.21
  Top w12: v1(2655,-980) T2.15@2714.97,-980
  Bottom w15: R61.1@2630.8,-979.21 2654.21,-979.21 v1(2655,-980)
NetR62_1: R62.1 T2.18 | length 85.6
  Top w8: v1(2655,-830) v1@2655.79,-829.21
  Top w12: v1@2655.79,-829.21 T2.18@2715.76,-829.21
  Bottom w15: R62.1@2630.8,-829.21 2654.21,-829.21 v1(2655,-830)
NetR63_1: R63.1 T2.21 | length 85.6
  Top w8: T2.21@2714.97,-680 T2.21@2715.76,-679.21
  Top w12: v1(2655,-680) T2.21@2714.97,-680
  Bottom w15: R63.1@2630.8,-679.21 2654.21,-679.21 v1(2655,-680)
NetR69_1: R69.1 T2.24 | length 85.6
  Top w8: v1(2655,-530) v1@2655.79,-529.21
  Top w12: v1@2655.79,-529.21 T2.24@2715.76,-529.21
  Bottom w8: v1@2654.21,-529.21 v1(2655,-530)
  Bottom w12: R69.1@2630.8,-529.21 v1@2654.21,-529.21
NetR73_2: R73.2 U4.42 | length 109.1
  Top w5: R73.2@1470,-1040 1490,-1020 1490,-990 1477.93,-977.93 U4.42@1477.93,-944.17
NetR77_2: R77.2 U4.39 | length 98.2
  Top w5: R77.2@1425,-1040 1425,-990 1430.68,-984.32 U4.39@1430.68,-944.17
NetR113_1: R113.1 R117.2 U6.4 | length 184.1
  Top w18: R117.2@120,-770 R113.1@120,-705 120,-695 125,-690 130,-695 U6.4@225,-695
NetR121_1: R121.1 T3.15 | length 90
  Top w12: T3.15@9875,-1184.96 v1(9875,-1125)
  Bottom w12: v1(9875,-1125) R121.1@9875,-1095
NetR122_1: R122.1 T3.18 | length 90
  Top w12: T3.18@10025,-1184.96 v1(10025,-1125)
  Bottom w12: v1(10025,-1125) R122.1@10025,-1095
NetR123_1: R123.1 T3.21 | length 90
  Top w12: T3.21@10175,-1184.96 v1(10175,-1125)
  Bottom w12: v1(10175,-1125) R123.1@10175,-1095
NetR129_1: R129.1 T3.24 | length 90
  Top w12: T3.24@10325,-1184.96 v1(10325,-1125)
  Bottom w12: v1(10325,-1125) R129.1@10325,-1095
NetR133_2: R133.2 U7.42 | length 128.6
  Top w8: R133.2@9270,-1008 9302,-1008 9312.17,-997.83 U7.42@9312.17,-915.59
NetR137_2: R137.2 U7.39 | length 141
  Top w5: R137.2@9163,-982 9164.5,-982 9185,-961.5 9237.64,-961.5 9264.88,-934.26 U7.39@9264.88,-914.96
NetR174_1: R174.1 R177.2 U9.4 | length 166.2
  Top w24: R177.2@7225,-535 R174.1@7290,-535 ; R174.1@7285,-530 R174.1@7290,-535 ; U9.4@7380,-525 7300,-525 R174.1@7290,-535
NetTP1_1: TP1.1 U1.46 | length 90.8
  Top w5: U1.46@5570.92,-889.17 5570.92,-945.92 TP1.1@5585.85,-960.85 TP1.1@5595,-970
NetTP2_1: TP2.1 U4.46 | length 92.1
  Top w5: U4.46@1540.92,-944.17 1540.92,-1013.42 1550,-1022.5 TP2.1@1560,-1022.5
NetTP3_1: TP3.1 U7.46 | length 222.5
  Top w5: U7.46@9375.16,-915.59 9375.16,-955.16 9405,-985 9405,-1055 TP3.1@9455,-1105
RGMII_RXCK: JP1.C11 R4.1 | length 848.4
  Top w5: JP1.C11@5387.8,-315.35 5399.44,-327 5428,-327 5435,-320 5435,-281 5429,-275 5350,-275 5340,-285 5340,-350 5345,-355 5399,-355 5404,-360 5404,-365.5 5401,-368.5 5306.5,-368.5 5300,-375 5300,-385 5305,-390 5336.67,-390 cw(c5336.67,-394.5) 5341.17,-394.5 5341.17,-395.5 cw(c5336.67,-395.5) 5336.67,-400 5297.7,-400 ccw(c5297.7,-404.5) 5293.2,-404.5 5293.2,-405.5 ccw(c5297.7,-405.5) 5297.7,-410 5335,-410 5337.19,-412.19 5337.19,-426.81 5334,-430 5297.7,-430 ccw(c5297.7,-434.5) 5293.2,-434.5 5293.2,-435.5 ccw(c5297.7,-435.5) 5297.7,-440 5314.5,-440 cw(c5314.5,-444.5) 5319,-444.5 5319,-464 5331,-476 5411,-476 5415,-480 5415,-489 R4.1@5405,-499
  Bottom w5: JP1.C11@5382,-321.15 JP1.C11@5387.8,-315.35
RGMII_RXD0: JP1.C7 R6.1 | length 749.6
  Top w5: R6.1@5675,-409 v1(5675,-385)
  Bottom w5: JP1.C7@4987.8,-315.35 5038.94,-366.5 5506.5,-366.5 5511.5,-371.5 5563.5,-371.5 5575,-360 5650,-360 v1(5675,-385)
RGMII_RXD1: JP1.C8 R7.1 | length 760.5
  Top w5: R7.1@5540,-409 v1(5540,-355)
  Bottom w5: JP1.C8@5087.8,-315.35 5087.8,-317.2 5070,-335 5055,-335 5040,-320 5040,-270 5050,-260 5530,-260 5540,-270 v1(5540,-355)
RGMII_RXD2: JP1.C9 R8.1 | length 755.4
  Top w5: v1(5445,-350) 5455,-360 5495,-360 5510,-375 5510,-394 R8.1@5495,-409
  Bottom w5: JP1.C9@5187.8,-315.35 5190,-317.56 5190,-350 5185,-355 5150,-355 5140,-345 5140,-280 5150,-270 5225.75,-270 cw(c5225.75,-276.75) 5232.5,-276.75 5232.5,-293.25 ccw(c5239.25,-293.25) 5239.25,-300 5240.75,-300 ccw(c5240.75,-293.25) 5247.5,-293.25 5247.5,-276.75 cw(c5254.25,-276.75) 5254.25,-270 5325.75,-270 cw(c5325.75,-276.75) 5332.5,-276.75 5332.5,-293.25 ccw(c5339.25,-293.25) 5339.25,-300 5340.75,-300 ccw(c5340.75,-293.25) 5347.5,-293.25 5347.5,-276.75 cw(c5354.25,-276.75) 5354.25,-270 5440,-270 5445,-275 v1(5445,-350)
RGMII_RXD3: JP1.C10 R9.1 | length 728.4
  Top w5: JP1.C10@5287.8,-315.35 5287.8,-322.8 5311,-346 5323,-346 5330,-339 5330,-205 5335,-200 5345,-200 5349.3,-204.3 5349.3,-252 5361.3,-264 5420,-264 5429,-255 5429,-224 5434,-219 5441,-219 5447,-225 5447,-250.75 ccw(c5453.75,-250.75) 5453.75,-257.5 5500.25,-257.5 cw(c5500.25,-264.25) 5507,-264.25 5507,-265.75 cw(c5500.25,-265.75) 5500.25,-272.5 5450.5,-272.5 ccw(c5450.5,-276) 5447,-276 5447,-323 5427,-343 5427,-401 5419,-409 R9.1@5405,-409
RGMII_RXDV: JP1.C12 R5.1 | length 865.6
  Top w5: JP1.C12@5487.8,-315.35 5509.44,-337 5529,-337 5537,-329 5537,-279 5546,-270 5627.75,-270 ccw(c5627.75,-263.25) 5634.5,-263.25 5634.5,-236.75 cw(c5641.25,-236.75) 5641.25,-230 5642.75,-230 cw(c5642.75,-236.75) 5649.5,-236.75 5649.5,-263.25 ccw(c5656.25,-263.25) 5656.25,-270 5715,-270 5730,-285 5730,-350.75 ccw(c5736.75,-350.75) 5736.75,-357.5 5788.25,-357.5 cw(c5788.25,-364.25) 5795,-364.25 5795,-365.75 cw(c5788.25,-365.75) 5788.25,-372.5 5697.86,-372.5 ccw(c5697.86,-379.25) 5691.11,-379.25 5691.11,-380.75 ccw(c5697.86,-380.75) 5697.86,-387.5 5723.25,-387.5 cw(c5723.25,-394.25) 5730,-394.25 5730,-413 cw(c5723.5,-413) 5723.5,-419.5 5706.75,-419.5 ccw(c5706.75,-426.25) 5700,-426.25 5700,-427.75 ccw(c5706.75,-427.75) 5706.75,-434.5 5723.25,-434.5 cw(c5723.25,-441.25) 5730,-441.25 5730,-456 5687,-499 R5.1@5675,-499
RGMII_TXCKOUT: JP1.A11 U1.22 | length 1445.8
  Top w5: JP1.A11@5387.8,-115.35 5413.15,-90 5430,-90 5440,-100 5440,-150 5425,-165 5265,-165 5245,-185 5245,-250.75 ccw(c5251.75,-250.75) 5251.75,-257.5 5308.25,-257.5 cw(c5308.25,-264.25) 5315,-264.25 5315,-265.75 cw(c5308.25,-265.75) 5308.25,-272.5 5251.75,-272.5 ccw(c5251.75,-279.25) 5245,-279.25 5245,-360.75 ccw(c5251.75,-360.75) 5251.75,-367.5 5276.45,-367.5 cw(c5276.45,-374.25) 5283.2,-374.25 5283.2,-375.75 cw(c5276.45,-375.75) 5276.45,-382.5 5251.75,-382.5 ccw(c5251.75,-389.25) 5245,-389.25 5245,-390.75 ccw(c5251.75,-390.75) 5251.75,-397.5 5276.45,-397.5 cw(c5276.45,-404.25) 5283.2,-404.25 5283.2,-405.75 cw(c5276.45,-405.75) 5276.45,-412.5 5251.75,-412.5 ccw(c5251.75,-419.25) 5245,-419.25 5245,-420.75 ccw(c5251.75,-420.75) 5251.75,-427.5 5276.45,-427.5 cw(c5276.45,-434.25) 5283.2,-434.25 5283.2,-435.75 cw(c5276.45,-435.75) 5276.45,-442.5 5251.75,-442.5 ccw(c5251.75,-449.25) 5245,-449.25 5245,-450.75 ccw(c5251.75,-450.75) 5251.75,-457.5 5276.45,-457.5 cw(c5276.45,-464.25) 5283.2,-464.25 5283.2,-465.75 cw(c5276.45,-465.75) 5276.45,-472.5 5251.75,-472.5 ccw(c5251.75,-479.25) 5245,-479.25 5245,-480.75 ccw(c5251.75,-480.75) 5251.75,-487.5 5276.45,-487.5 cw(c5276.45,-494.25) 5283.2,-494.25 5283.2,-495.75 cw(c5276.45,-495.75) 5276.45,-502.5 5251.75,-502.5 ccw(c5251.75,-509.25) 5245,-509.25 5245,-550 5260.53,-565.53 ccw(c5265.3,-560.76) 5270.08,-565.53 cw(c5274.85,-570.3) 5279.62,-565.53 5280.68,-566.59 cw(c5275.91,-571.36) 5280.68,-576.14 ccw(c5285.46,-580.91) 5280.68,-585.68 5315,-620 5445,-620 5460.68,-635.68 U1.22@5460.68,-659.25 U1.22@5460.68,-647.39
RGMII_TXD0: JP1.A7 U1.23 | length 1443.4
  Top w5: v1(5230,-165) 5235,-170 5235,-250.75 cw(c5228.25,-250.75) 5228.25,-257.5 5177.23,-257.5 ccw(c5177.23,-264.25) 5170.48,-264.25 5170.48,-265.75 ccw(c5177.23,-265.75) 5177.23,-272.5 5228.25,-272.5 cw(c5228.25,-279.25) 5235,-279.25 5235,-470 cw(c5227.5,-470) 5227.5,-477.5 5174.75,-477.5 ccw(c5174.75,-485) 5167.25,-485 ccw(c5174.75,-485) 5174.75,-492.5 5227.5,-492.5 cw(c5227.5,-500) 5235,-500 cw(c5227.5,-500) 5227.5,-507.5 5204.75,-507.5 ccw(c5204.75,-515) 5197.25,-515 ccw(c5204.75,-515) 5204.75,-522.5 5227.5,-522.5 cw(c5227.5,-530) 5235,-530 5235,-555 5310,-630 5435,-630 5444.93,-639.93 U1.23@5444.93,-659.25 U1.23@5444.93,-645.79
  Bottom w5: JP1.A7@4987.8,-115.35 4995,-108.15 4995,-80 4985,-70 4950,-70 4940,-80 4940,-155 4950,-165 v1(5230,-165)
RGMII_TXD1: JP1.A8 U1.24 | length 1443.4
  Top w5: JP1.A8@5087.8,-115.35 5087.8,-107.2 5110,-85 5135,-85 5140,-90 5140,-355 ccw(c5147.5,-355) 5147.5,-362.5 5212.5,-362.5 cw(c5212.5,-370) 5220,-370 cw(c5212.5,-370) 5212.5,-377.5 5137.5,-377.5 ccw(c5137.5,-385) 5130,-385 ccw(c5137.5,-385) 5137.5,-392.5 5212.5,-392.5 cw(c5212.5,-400) 5220,-400 cw(c5212.5,-400) 5212.5,-407.5 5089.75,-407.5 ccw(c5089.75,-415) 5082.25,-415 ccw(c5089.75,-415) 5089.75,-422.5 5212.5,-422.5 cw(c5212.5,-430) 5220,-430 cw(c5212.5,-430) 5212.5,-437.5 5147.5,-437.5 ccw(c5147.5,-445) 5140,-445 5140,-475 5305,-640 5345,-640 cw(c5345,-647.5) 5352.5,-647.5 5352.5,-658.2 ccw(c5360,-658.2) 5360,-665.7 ccw(c5360,-658.2) 5367.5,-658.2 5367.5,-647.5 cw(c5375,-647.5) 5375,-640 5420,-640 5429.19,-649.19 U1.24@5429.19,-659.25
RGMII_TXD2: JP1.A9 U1.25 | length 1443.4
  Top w5: JP1.A9@5187.8,-115.35 5192.44,-120 5230,-120 5240,-110 5240,-80 5230,-70 5065,-70 5045,-90 5045,-150 ccw(c5052.5,-150) 5052.5,-157.5 5114.67,-157.5 cw(c5114.67,-165) 5122.17,-165 cw(c5114.67,-165) 5114.67,-172.5 5052.5,-172.5 ccw(c5052.5,-180) 5045,-180 5045,-250 ccw(c5052.5,-250) 5052.5,-257.5 5082.5,-257.5 cw(c5082.5,-265) 5090,-265 cw(c5082.5,-265) 5082.5,-272.5 5052.5,-272.5 ccw(c5052.5,-280) 5045,-280 5045,-355 ccw(c5052.5,-355) 5052.5,-362.5 5117.5,-362.5 cw(c5117.5,-370) 5125,-370 cw(c5117.5,-370) 5117.5,-377.5 5052.5,-377.5 ccw(c5052.5,-385) 5045,-385 5045,-395 5337.6,-687.6 U1.25@5400.84,-687.6
RGMII_TXD3: JP1.A10 U1.26 | length 1443.4
  Top w5: JP1.A10@5287.8,-115.35 5329.65,-115.35 5335,-110 5335,-65 5330,-60 5050,-60 5035,-75 5035,-150 cw(c5027.5,-150) 5027.5,-157.5 4998.57,-157.5 ccw(c4998.57,-165) 4991.07,-165 ccw(c4998.57,-165) 4998.57,-172.5 5027.5,-172.5 cw(c5027.5,-180) 5035,-180 5035,-250 cw(c5027.5,-250) 5027.5,-257.5 4997.5,-257.5 ccw(c4997.5,-265) 4990,-265 ccw(c4997.5,-265) 4997.5,-272.5 5027.5,-272.5 cw(c5027.5,-280) 5035,-280 5035,-350 cw(c5027.5,-350) 5027.5,-357.5 4999.75,-357.5 ccw(c4999.75,-365) 4992.25,-365 ccw(c4999.75,-365) 4999.75,-372.5 5027.5,-372.5 cw(c5027.5,-380) 5035,-380 5035,-399.14 5339.2,-703.34 U1.26@5400.84,-703.34
RGMII_TXEN: JP1.A12 U1.27 | length 1443.7
  Top w5: U1.27@5400.84,-719.09 5374.09,-719.09 5368.34,-713.34 5335.06,-713.34 5006.72,-385 4994.51,-385 4983.26,-373.75 4983.26,-373.26 4945,-335 4945,-95 4990,-50 5422.44,-50 JP1.A12@5487.8,-115.35
UART1_RXD: J3.26 R52.2 R205.1 R206.1 | length 951.4
  Top w5: R52.2@4650,-510 4670,-530 4670,-640 R206.1@4645,-665 R205.1@4645,-705 4670,-730 4670,-810 4931.5,-1071.5 5076.5,-1071.5 5098.43,-1093.43 J3.26@5098.43,-1141.73 J3.26@5098.43,-1113.43
UART1_TXD: J3.25 R53.2 R204.1 R207.1 | length 1031.8
  Top w5: R53.2@4690,-510 4680,-520 4680,-640 R207.1@4705,-665 R204.1@4705,-705 4680,-730 4680,-805 4936.5,-1061.5 5087.95,-1061.5 5140,-1113.55 5140,-1178.9 J3.25@5098.43,-1220.47
pads on no net: J2.15 J2.16 J2.17 J2.18 J2.23 J2.24 JP1.0 JP1.0/2 JP1.A14 JP1.A15 JP1.A16 JP1.B5 JP1.B6 JP1.C4 JP1.C5 JP1.C13 JP1.C14 JP1.C15 JP1.C16 JP2.0 JP2.0/2 JP2.A14 JP2.A15 JP2.A16 JP2.B5 JP2.B6 JP2.C4 JP2.C5 JP2.C13 JP2.C14 JP2.C15 JP2.C16 JP3.0 JP3.0/2 JP3.A14 JP3.A15 JP3.A16 JP3.B5 JP3.B6 JP3.C4 JP3.C5 JP3.C13 JP3.C14 JP3.C15 JP3.C16 M1.1 M2.1 M3.1 M4.1 M5.1 M6.1 M7.1 M8.1 U1.12 U1.43 U4.12 U4.43 U7.12 U7.43

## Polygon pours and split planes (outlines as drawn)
12VIN on Top "GND" (hatched 90Degree grid 5 track 5, remove dead copper, pour order 1000): 9720,90 9850,90 10445,90 10545,-10 10550,-15 10550,-385 10240,-385 10185,-330 10100,-245 10015,-245 9800,-30 9725,45 9720,45 9720,90
GND on Top "GND" (hatched 90Degree grid 5 track 5, remove dead copper, pour order 1000): -50,169.29 -180.71,169.29 -190,160 -196.85,153.15 -196.85,120 -196.85,-1388.15 -175,-1410 -171.85,-1413.15 -130,-1413.15 11391.85,-1413.15 11415,-1390 11417.32,-1387.68 11417.32,-1320 11417.32,142.68 11390,170 11389.29,169.29 11330,169.29 -50,169.29
GND on Bottom "GND" (hatched 90Degree grid 5 track 5, remove dead copper, pour order 1001): -120,169.29 -175.71,169.29 -196.85,148.15 -196.85,120 -196.85,-1393.15 -180,-1410 -176.85,-1413.15 -110,-1413.15 11386.85,-1413.15 11415,-1385 11417.32,-1382.68 11417.32,-1355 11417.32,142.68 11390,170 11389.29,169.29 11330,169.29 -120,169.29

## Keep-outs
Keep-Out Layer:
  pour cut-out: 5945,-530 5945,-1255 6025,-1334 6964,-1334 7210,-1088 7266,-1031 7900,-1030 7940,-1070 7940,-1280 7965,-1305 7975,-1295 8300,-1295 8300,-1060 8095,-855 7115,-855 6975,-995 6935,-1036 6667,-1036 6633,-988 6635,-975 6635,-530
  pour cut-out: 2050,-475 2782,-475 2865,-565 3115,-815 4285,-815 4455,-980 4455,-1255 4430,-1280 4110,-1280 4110,-1070 4060,-1020 3215,-1020 3115,-1120 2770,-1120 2720,-1170 2050,-1170
  pour cut-out: 8675,-1075 8745,-1005 8905,-1005 8935,-1035 9000,-1035 9000,-1040 9125,-1165 9150,-1165 9200,-1215 9405,-1215 9445,-1175 9555,-1175 9610,-1130 9705,-1035 9700,-560 10395,-560 10395,-585 10400,-590 10400,-1120 10355,-1165 10355,-1220 10180,-1395 8900,-1395 8790,-1285 8685,-1285 8675,-1275
  lines w5: -196.85,-1370 ccw(c-154.35,-1370.65) -155,-1413.15 11365,-1413.15 ccw(c11369.59,-1365.41) 11417.32,-1370 11417.32,90 ccw(c11334.02,85.98) 11330,169.29 10090,169.29 10090,110.24 7940,110.24 7940,169.29 6215,169.29 6215,110.24 4065,110.24 4065,169.29 2335,169.29 2335,110.24 185,110.24 185,169.29 -145,169.29 ccw(c-146.28,118.72) -196.85,120 -196.85,-1370

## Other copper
Top:
  pour cut-out: 7990,-655 8090,-655 8090,-740 8095,-745 8090,-750 7990,-750
  pour cut-out: 3925,-650 4035,-650 4035,-740 3925,-740
  pour cut-out: 550,-1125 675,-1125 675,-1215 550,-1215
  region net 5V0: 3565,50 3625,-10 3625,-25 3600,-50 3575,-50 3525,0 3525,10
  region net NetJP3_B1: 8165,-175 7975,-365 7600,-365 7600,-534.53 7600.47,-535 7925,-535 8200,-260 8300,-260 8300,-175
  pour cut-out: 7310,-360 7635,-360 7635,-560 7310,-560
  pour cut-out: 135,-535 535,-535 535,-735 135,-735
  pour cut-out: 3730,-255 3735,-260 3735,-455 3325,-455 3325,-255
  region net C3V3D: 7995,-585 8070,-585 8080,-575 8080,-495 8240,-495 8320,-575 8320,-760 8085,-760 8085,-675 8070,-660 7995,-660
  region net B3V3D: 570,-1065 645,-1065 660,-1050 660,-960 845,-960 895,-1010 895,-1175 850,-1220 665,-1220 665,-1135 645,-1115 570,-1115
  region net A3V3D: 3915,-540 3990,-540 4015,-515 4015,-440 4165,-440 4240,-515 4240,-640 4165,-715 4015,-715 4015,-640 3990,-615 3915,-615
  region net NetJP1_B1: 4275,-175 4175,-275 3750,-275 3730,-255 3700,-255 3700,-430 3705,-425 3790,-425 3815,-400 4225,-400 4360,-265 4620,-265 4620,-175
  region net NetJP2_B1: 725,-165 405,-165 350,-225 350,-390 445,-485 445,-705 545,-705 550,-700 550,-450 460,-360 460,-280 470,-270 725,-270
  region net 5V0: 6315,-10 6220,-10 6220,-70 6315,-70
Bottom:
  region net 5V0: 7930,-180 7840,-180 7840,-240 7930,-240
  region net 5V0: 3612,-1 3573,38 3544,38 3532,26 3518,11 3571,-42 3577,-36 3589,-36 3613,-12 3612,-11

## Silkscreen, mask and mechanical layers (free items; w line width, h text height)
Silkscreen Top:
  drawing of 469 lines, arcs and shapes, not listed
  text "GN-1846-B-V2" at 3120,-875 h27.56
  text "2017-12-07" at 3122,-951 h27.56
